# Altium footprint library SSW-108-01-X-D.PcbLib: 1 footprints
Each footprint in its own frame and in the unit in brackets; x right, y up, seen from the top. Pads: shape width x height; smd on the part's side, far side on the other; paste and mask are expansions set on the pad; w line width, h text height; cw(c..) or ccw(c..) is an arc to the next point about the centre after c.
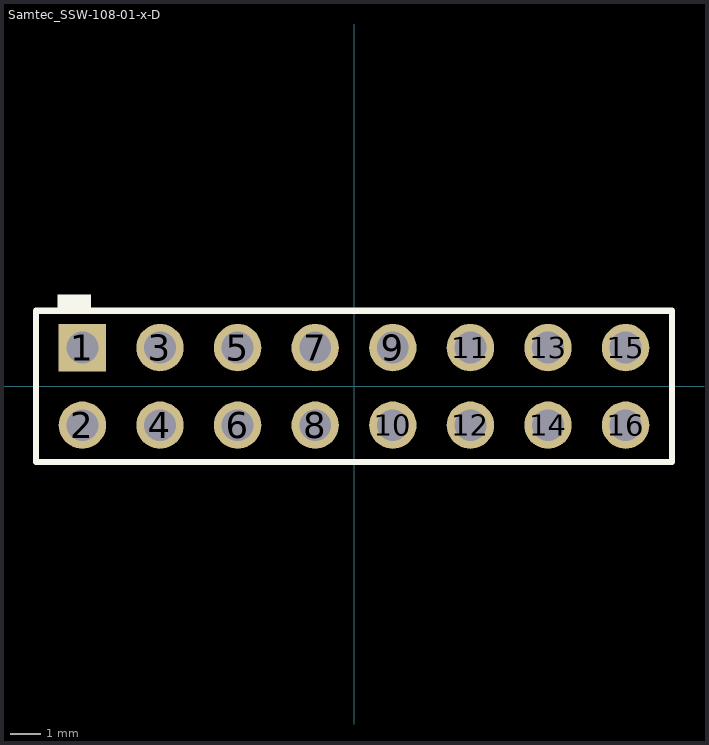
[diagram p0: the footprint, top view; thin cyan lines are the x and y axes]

## Samtec_SSW-108-01-x-D [mm] "Receptacle, 2.54mm, 8x2, TH"
height 8.52
pads (16):
  rect 1.55x1.55 hole 1.04: 1(-8.89,1.27)
  round 1.55 hole 1.04: 2(-8.89,-1.27) 3(-6.35,1.27) 4(-6.35,-1.27) 5(-3.81,1.27) 6(-3.81,-1.27) 7(-1.27,1.27) 8(-1.27,-1.27) 9(1.27,1.27) 10(1.27,-1.27) 11(3.81,1.27) 12(3.81,-1.27) 13(6.35,1.27) 14(6.35,-1.27) 15(8.89,1.27) 16(8.89,-1.27)
Top Overlay:
  region: -8.6,2.477 -8.6,3 -9.7,3 -9.7,2.477
  lines w0.2: -10.414,-2.476 10.414,-2.476 10.414,2.477 -10.414,2.477 -10.414,-2.476
M5 Assembly Top:
  lines w0.1: -10.414,-2.476 -10.414,2.477 10.414,2.477 10.414,-2.476 -10.414,-2.476
  text ".Designator" at -1.7,-0.4 h1.02
3D body: height 8.51, standoff -2.64, extent -10.414,-2.476 10.414,2.477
